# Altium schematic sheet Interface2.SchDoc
size A4
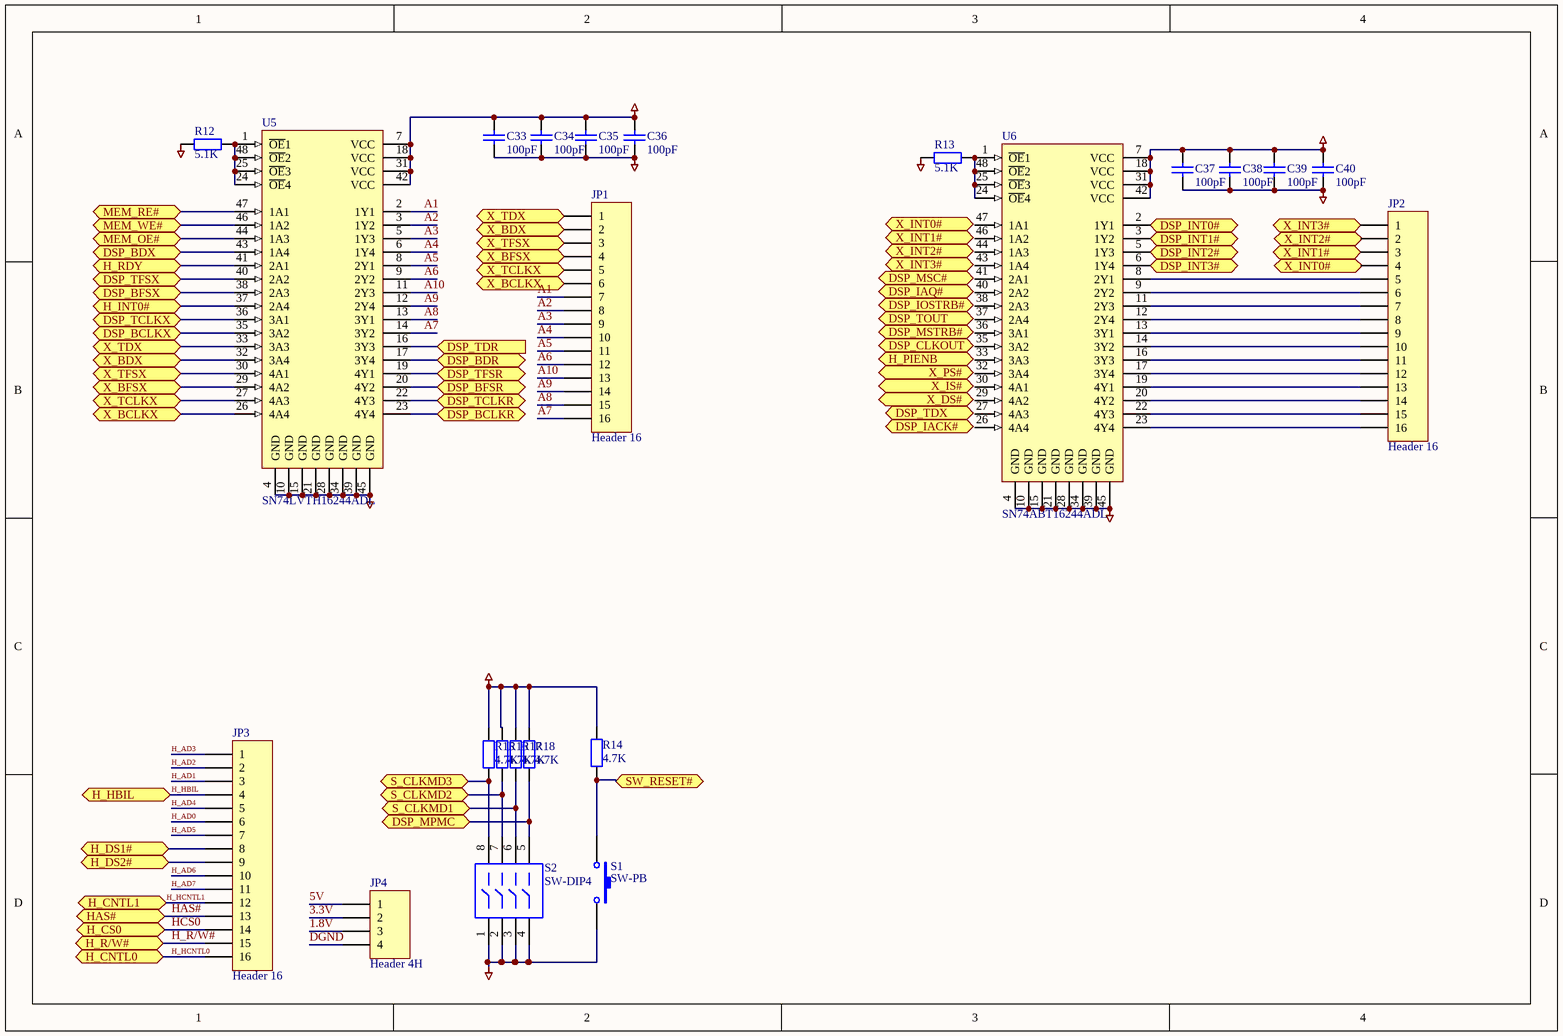
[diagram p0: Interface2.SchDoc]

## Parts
C33  100pF  [CC2012-0805]
C34  100pF  [CC2012-0805]
C35  100pF  [CC2012-0805]
C36  100pF  [CC2012-0805]
C37  100pF  [CC2012-0805]
C38  100pF  [CC2012-0805]
C39  100pF  [CC2012-0805]
C40  100pF  [CC2012-0805]
JP1  Header 16  [HDR1X16]
JP2  Header 16  [HDR1X16]
JP3  Header 16  [HDR1X16]
JP4  Header 4H  [HDR1X4H]
R12  5.1K  [R2012-0805]
R13  5.1K  [R2012-0805]
R14  4.7K  [R2012-0805]
R15  4.7K  [R2012-0805]
R16  4.7K  [R2012-0805]
R17  4.7K  [R2012-0805]
R18  4.7K  [R2012-0805]
S1  SW-PB  [SPST-2]
S2  SW-DIP4  [DIP-8]
U5  SN74LVTH16244ADL  [SSO-G48]
U6  SN74ABT16244ADL  [SSO-G48]

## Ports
DSP_BCLKR, DSP_BCLKX, DSP_BDR, DSP_BDX, DSP_BFSR, DSP_BFSX, DSP_CLKOUT, DSP_IACK#, DSP_IAQ#, DSP_INT0#, DSP_INT1#, DSP_INT2#, DSP_INT3#, DSP_IOSTRB#, DSP_MPMC, DSP_MSC#, DSP_MSTRB#, DSP_TCLKR, DSP_TCLKX, DSP_TDR (in), DSP_TDX, DSP_TFSR, DSP_TFSX, DSP_TOUT, H_CNTL0, H_CNTL1, H_CS0, H_DS1#, H_DS2#, H_HBIL, H_INT0#, H_PIENB, H_R/W#, H_RDY, HAS#, MEM_OE#, MEM_RE#, MEM_WE#, S_CLKMD1, S_CLKMD2, S_CLKMD3, SW_RESET#, X_BCLKX, X_BDX, X_BFSX, X_DS#, X_INT0#, X_INT1#, X_INT2#, X_INT3#, X_IS#, X_PS#, X_TCLKX, X_TDX, X_TFSX

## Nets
3.3V: C33.2 C34.2 C35.2 C36.2 C37.2 C38.2 C39.2 C40.2 JP4.2 R14.2 R15.2 R16.2 R17.2 R18.2 U5.7(VCC) U5.18(VCC) U5.31(VCC) U5.42(VCC) U6.7(VCC) U6.18(VCC) U6.31(VCC) U6.42(VCC)
DGND: C33.1 C34.1 C35.1 C36.1 C37.1 C38.1 C39.1 C40.1 JP4.4 R12.1 R13.1 S2.1 U5.4(GND) U5.10(GND) U5.15(GND) U5.21(GND) U5.28(GND) U5.34(GND) U5.39(GND) U5.45(GND) U6.4(GND) U6.10(GND) U6.15(GND) U6.21(GND) U6.28(GND) U6.34(GND) U6.39(GND) U6.45(GND)
1.8V: JP4.3
5V: JP4.1
A1: JP1.7 U5.2(1Y1)
A2: JP1.8 U5.3(1Y2)
A3: JP1.9 U5.5(1Y3)
A4: JP1.10 U5.6(1Y4)
A5: JP1.11 U5.8(2Y1)
A6: JP1.12 U5.9(2Y2)
A7: JP1.16 U5.14(3Y2)
A8: JP1.15 U5.13(3Y1)
A9: JP1.14 U5.12(2Y4)
A10: JP1.13 U5.11(2Y3)
DSP_BCLKR: U5.23(4Y4) ; port DSP_BCLKR
DSP_BCLKX: U5.35(3A2) ; port DSP_BCLKX
DSP_BDR: U5.17(3Y4) ; port DSP_BDR
DSP_BDX: U5.43(1A4) ; port DSP_BDX
DSP_BFSR: U5.20(4Y2) ; port DSP_BFSR
DSP_BFSX: U5.38(2A3) ; port DSP_BFSX
DSP_INT0#: U6.2(1Y1) ; port DSP_INT0#
DSP_INT1#: U6.3(1Y2) ; port DSP_INT1#
DSP_INT2#: U6.5(1Y3) ; port DSP_INT2#
DSP_INT3#: U6.6(1Y4) ; port DSP_INT3#
DSP_MPMC: R18.1 S2.5 ; port DSP_MPMC
DSP_TCLKR: U5.22(4Y3) ; port DSP_TCLKR
DSP_TCLKX: U5.36(3A1) ; port DSP_TCLKX
DSP_TDR: U5.16(3Y3) ; port DSP_TDR
DSP_TFSR: U5.19(4Y1) ; port DSP_TFSR
DSP_TFSX: U5.40(2A2) ; port DSP_TFSX
H_AD0: JP3.6
H_AD1: JP3.3
H_AD2: JP3.2
H_AD3: JP3.1
H_AD4: JP3.5
H_AD5: JP3.7
H_AD6: JP3.10
H_AD7: JP3.11
H_DS1#: JP3.8 ; port H_DS1#
H_DS2#: JP3.9 ; port H_DS2#
H_HBIL: JP3.4 ; port H_HBIL
H_HCNTL0: JP3.16 ; port H_CNTL0
H_HCNTL1: JP3.12 ; port H_CNTL1
H_INT0#: U5.37(2A4) ; port H_INT0#
H_R/W#: JP3.15 ; port H_R/W#
H_RDY: U5.41(2A1) ; port H_RDY
HAS#: JP3.13 ; port HAS#
HCS0: JP3.14 ; port H_CS0
MEM_OE#: U5.44(1A3) ; port MEM_OE#
MEM_RE#: U5.47(1A1) ; port MEM_RE#
MEM_WE#: U5.46(1A2) ; port MEM_WE#
S_CLKMD1: R17.1 S2.6 ; port S_CLKMD1
S_CLKMD2: R16.1 S2.7 ; port S_CLKMD2
S_CLKMD3: R15.1 S2.8 ; port S_CLKMD3
SW_RESET#: R14.1 S1.1 ; port SW_RESET#
X_BCLKX: JP1.6 U5.26(4A4) ; port X_BCLKX
X_BDX: JP1.2 U5.32(3A4) ; port X_BDX
X_BFSX: JP1.4 U5.29(4A2) ; port X_BFSX
X_INT1#: JP2.3 ; port X_INT1#
X_INT3#: JP2.1 ; port X_INT3#
X_TCLKX: JP1.5 U5.27(4A3) ; port X_TCLKX
X_TDX: JP1.1 U5.33(3A3) ; port X_TDX
X_TFSX: JP1.3 U5.30(4A1) ; port X_TFSX
NetJP2_5: JP2.5 U6.8(2Y1)
NetJP2_6: JP2.6 U6.9(2Y2)
NetJP2_7: JP2.7 U6.11(2Y3)
NetJP2_8: JP2.8 U6.12(2Y4)
NetJP2_9: JP2.9 U6.13(3Y1)
NetJP2_10: JP2.10 U6.14(3Y2)
NetJP2_11: JP2.11 U6.16(3Y3)
NetJP2_12: JP2.12 U6.17(3Y4)
NetJP2_13: JP2.13 U6.19(4Y1)
NetJP2_14: JP2.14 U6.20(4Y2)
NetJP2_15: JP2.15 U6.22(4Y3)
NetJP2_16: JP2.16 U6.23(4Y4)
NetR12_2: R12.2 U5.1(~{OE}1) U5.24(~{OE}4) U5.25(~{OE}3) U5.48(~{OE}2)
NetR13_2: R13.2 U6.1(~{OE}1) U6.24(~{OE}4) U6.25(~{OE}3) U6.48(~{OE}2)
NetS1_2: S1.2 S2.2 S2.3 S2.4

Not connected (* = marked no-connect by the designer): JP2 2 4; U6 26(4A4) 27(4A3) 29(4A2) 30(4A1) 32(3A4) 33(3A3) 35(3A2) 36(3A1) 37(2A4) 38(2A3) 40(2A2) 41(2A1) 43(1A4) 44(1A3) 46(1A2) 47(1A1)

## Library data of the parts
C33-C40 = Cap: Capacitor; Manufacturer: Generic Components; Class I: Passive
JP1-JP3 = Header 16: Header, 16-Pin; Manufacturer: Generic Components; Class I: Connector
JP4 = Header 4H: Header, 4-Pin,  Right Angle; Manufacturer: Generic Components; Class I: Connector
R12-R18 = Res2: Resistor; Manufacturer: Generic Components; Class I: Passive
S1 = SW-PB: Switch; Manufacturer: Generic Components
S2 = SW-DIP4: DIP Switch; Manufacturer: Generic Components
U5 = SN74LVTH16244ADL: 3.3-V ABT 16-Bit Buffer/Driver with 3-State Outputs; Manufacturer: Texas Instruments; Package Information: Latest Revision: Jan-1998; Class I: Logic; Class II: Buffer/Line Driver
U6 = SN74ABT16244ADL: 16-Bit Buffer/Driver with 3-State Outputs; Manufacturer: Texas Instruments; Package Information: Latest Revision: Jan-1998; Class I: Logic; Class II: Buffer/Line Driver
